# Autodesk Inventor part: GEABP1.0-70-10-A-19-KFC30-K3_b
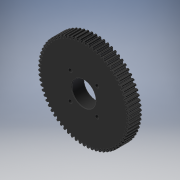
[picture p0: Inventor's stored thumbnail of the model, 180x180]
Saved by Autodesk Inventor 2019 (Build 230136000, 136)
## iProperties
Created: 2022-11
Part Number: GEABP1.0-70-10-A-19-KFC30-K3_b
Material: Generic
Catalog Web Link: www.cadenas.de
Description: GEABM, GEABMS, GEABMT, GEABP, GEABPS, GEABPT, GEABA, GEABAS, GEABAT_body-Plastic Spur Gears - Pressure Angle 20 Degrees, Module 0.5/0.8/1.0/1.5/2.0/2.5/3.0
Vendor: MISUMI
Document SubType Name: Modeling
Designer: psAdmin
Manufacturer: MISUMI
Mass: 35.1523 g
Surface Area: 122.756 cm^2
Volume: 35.1523 cm^3
Density: 1 g/cm^3
Appearance: PSOLRGB-175-175-175
Category: PARTsolutions
Company: MISUMI
Title: GEABP1.0-70-10-A-19-KFC30-K3
Author: Cadenas PARTsolutions
Comments: Plastic Spur Gears - Pressure Angle 20 Degrees, Module 0.5/0.8/1.0/1.5/2.0/2.5/3.0
PSOL_IDENT_0: {$CADENAS_DATA/23d-libs/misumi/metric/54_spur_gears/geabms20/geabms20.prj},408 {VTYP=3D},{NB=GEABP1.
PSOL_IDENT_1: 0-70-10-A-19-KFC30-K3_b},{LINA=GEABP1.0-70-10-A-19-KFC30-K3},{NN=GEABM, GEABMS, GEABMT, GEABP, GEABP
PSOL_IDENT_2: S, GEABPT, GEABA, GEABAS, GEABAT_body},{DATE=17.10.2022 23:48:33},{GEOMDATE=14.09.2022 05:11:00},{VE
PSOL_IDENT_3: RSION=},{LINEID=30},{WBVAR=MATSG,MATCR,NT,B,TS,PS,ALT1,ALT2,TPC,ALT11,ALT10,BS,ALT3,Z,J,ALT4,Q,R,S,T
PSOL_IDENT_4: ,ALT5,LFC,LTC,MALT5,ALT6,KFC,KTC,K},{WBNUMERIC=NT,B,BS,Z,J,Q,R,S,T,LFC,LTC,KFC,KTC,K}  {NB=GEABP1.0-
PSOL_IDENT_5: 70-10-A-19-KFC30-K3_b},{LINA=GEABP1.0-70-10-A-19-KFC30-K3},{KT=DUMMY},{PN=GEABP1.0-70-10-A-19-KFC30-
PSOL_IDENT_6: K3},{TYPE=GEABP},{MATSG=PW},{MATSGALG='MCN','MC Nylon','PW','Polyacetal White','PB','Polyacetal Blue'
PSOL_IDENT_7: },{MATCR=},{MATCRALG='','-','S45C','1045 Carbon Steel','SUS304','304 Stainless Steel'},{MOD=1.0},{MO
PSOL_IDENT_8: D1=1.0},{NT=70},{NTALG=15,16,18,20,22,24,25,26,28,30,32,35,36,40,45,48,50,55,60,70,75,80,90,100,120}
PSOL_IDENT_9: ,{B=10},{BALG=10,15},{TS=A},{TSALG='A','A','B','B'},{TSPN=-A},{PS=19},{PSALG='10','10','11','11','12'
PSOL_IDENT_10: ,'12','13','13','14','14','15','15','16','16','17','17','18','18','19','19','20','20','21','21','22'
PSOL_IDENT_11: ,'22','23','23','24','24','25','25','26','26','27','27','28','28'},{PSCRL='10','10','11','11','12','
PSOL_IDENT_12: 12','13','13','14','14','15','15','16','16','17','17','18','18','19','19','20','20','21','21','22','
PSOL_IDENT_13: 22','23','23','24','24','25','25','26','26','27','27','28','28'},{PSCRW='10','10','12','12','15','15'
PSOL_IDENT_14: ,'20','20'},{DD=70.0},{DD05=35},{DD08=56},{DD10=70},{DD15=105},{DD20=0},{DD25=0},{DD30=0},{D=72.0},{
PSOL_IDENT_15: D05=36},{D08=57.6},{D10=72},{D15=108},{D20=0},{D25=0},{D30=0},{G=67.50},{G05=33.75},{G08=54},{G10=67
PSOL_IDENT_16: .5},{G15=101.25},{G20=0},{G25=0},{G30=0},{H=0.0},{L=0},{LL1=0},{LL2=0.0},{M=-},{M3D=0},{P=19.00},{DD
PSOL_IDENT_17: 1=0},{CIFR=15},{CIFM=0},{CIFK=0},{CIFTAP=0},{ALT1=},{ALT1ALG='','Not applicable'},{ALT1PN=},{ALT2=},
PSOL_IDENT_18: {ALT2ALG='','Not applicable'},{TPC=N/A},{TPCALG='N/A'},{ALT2PN=},{KC=0},{ALT11=},{ALT11ALG='','Not a
PSOL_IDENT_19: pplicable'},{ALT11PN=},{DEG=0},{ALT10=},{ALT10ALG= '','Not applicable' },{ALT10PN=},{BS=0.0},{BSALG=
PSOL_IDENT_20: 0},{BSMIN=3},{BSMINALG=3.000},{BSMAX=0},{LL13D=0},{LL23D=0},{LBS=10},{ALT3=},{ALT3ALG= '','w/o Stepp
PSOL_IDENT_21: ed Hole','DHL','with DHL (Stepped Hole)','DHR','with DHR (Stepped Hole)' },{ALT3PN=},{ZJPN=},{ALT31=
PSOL_IDENT_22: 1},{ALT32=1},{Z=0},{ZALG=0},{ZMINL=21},{ZMAXL=63},{ZMINR=21},{ZMAXR=63},{ZPN=},{J=0.0},{JALG=0},{JMI
PSOL_IDENT_23: N=2},{JMAX=0},{JPN=},{ALT4=},{ALT4ALG= '','w/o WDH (Both Ends Stepped Hole)','WDH','with WDH (Both E
PSOL_IDENT_24: nds Stepped Hole)' },{ALT4PN=},{QRSTPN=},{LB=10.000},{Q=0},{QALG=0},{QMIN=21},{QMAX=63},{QPN=},{R=0}
PSOL_IDENT_25: ,{RALG=0},{RMIN=21},{RMAX=63},{RPN=},{S=0},{SALG=0},{SMIN=3},{SMAX=4},{SPN=},{T=0},{TALG=0},{TMIN=3}
PSOL_IDENT_26: ,{TMAX=0},{TPN=},{ALT5=},{ALT5ALG= '','w/o Side Slotted Hole','LFC','with LFC (Side Slotted Hole)','
PSOL_IDENT_27: LTC','with LTC (Side Slotted Hole)' },{LFC=0},{LFCALG=0},{LTC=0},{LTCALG=0},{LPCDMIN=27},{LPCDMAX=60
PSOL_IDENT_28: },{LCMAX=63},{MALT5=N/A},{MALT5ALG= 'N/A' },{LCMAX2=60},{C=0.0},{ALT5PN=},{ALT6=KFC},{ALT6ALG= '','w
PSOL_IDENT_29: /o Side Through Hole','KFC','with KFC (Side Through Hole)','KTC','with KTC (Side Through Hole)' },{A
PSOL_IDENT_30: LT6PN=-KFC},{KFTCPN=30-K3},{KFC=30},{KFCALG=[26:60/1]},{KFCPN=30},{KTC=0},{KTCALG=[0]},{KTCPN=},{KPC
PSOL_IDENT_31: DMIN1=26},{KPCDMAX1=-7},{KPCDMIN2=7},{KPCDMAX2=60},{K=3.0},{KALG=[3:6/0.5]},{KPCD=30},{KPN=-K3},{SCR
PSOL_IDENT_32: EW=0},{SCREWL=0},{AG=0},{PCD=30},{SHN=4},{SHDEG1=45},{SHDEG2=90},{PZQRDD2=19},{D1=1.285714},{D2=2.57
PSOL_IDENT_33: 1429},{D3=20},{D4=0.1},{D5=11.666667},{D6=10.769231},{D7=0.85},{D8=0.5},{D9=0.82917},{S1=15},{S2=0.5
PSOL_IDENT_34: },{KR=15}
NB: GEABP1.0-70-10-A-19-KFC30-K3_b
NN: GEABM, GEABMS, GEABMT, GEABP, GEABPS, GEABPT, GEABA, GEABAS, GEABAT_body
NT: 70
NBSYN: $PN._b
LINA: GEABP1.0-70-10-A-19-KFC30-K3
CATALOG: Misumi
PN: GEABP1.0-70-10-A-19-KFC30-K3
MATSG: Polyacetal White
MATCR: -
MOD: 1.0
B: 10
TS: A
PS: 19
DD: 70
D: 72
G: 67.5
H: 0
L: 0
LL1: 0
LL2: 0
M: -
DD1: 0
ALT1: Not applicable
ALT2: Not applicable
TPC: N/A
ALT11: Not applicable
ALT10: Not applicable
BS: 0
ALT3: w/o Stepped Hole
Z: 0
J: 0
ALT4: w/o WDH (Both Ends Stepped Hole)
Q: 0
R: 0
S: 0
T: 0
ALT5: w/o Side Slotted Hole
LFC: 0
LTC: 0
MALT5: N/A
C: 0
ALT6: with KFC (Side Through Hole)
KFC: 30
KTC: 0
K: 3
SUPPLIER: MISUMI
ARTICLENO: GEABP1.0-70-10-A-19-KFC30-K3_b
BOMINFO: GEABP1.0-70-10-A-19-KFC30-K3
CREATOR: CADENAS GmbH
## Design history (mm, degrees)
sketch "_____3"
  geometry: L1 (10, 0)-(0, 0); L2 (0, 0)-(0, 35.5); L3 (0, 35.5)-(0.67, 38); L4 (0.67, 38)-(9.33, 38); L5 (9.33, 38)-(10, 35.5); L6 (10, 35.5)-(10, 0); L7 (10, 0)-(0, 0)
  constraints: 14 end point
revolve "Revolution1" sketch "_____3" stored, may be unused: angle "d0" = 360 deg
sketch "_____12"
  geometry: C1 r 144 at (0, 0); A1 r 0.1 centre (-35.877, 1.285) between (-35.977, 1.288) and (-35.921, 1.195); A2 r 11.667 centre (-30.756, 11.656) between (-35.921, 1.195) and (-34.991, 0.785); A3 r 0.829 centre (-34.69, 1.558) between (-34.991, 0.785) and (-34.876, 0.75); A4 r 10.769 centre (-37.286, -9.746) between (-34.102, 0.542) and (-34.876, 0.75); A5 r 0.5 centre (-34.25, 0.064) between (-33.75, 0.063) and (-34.102, 0.542); A6 r 33.75 centre (0, 0) between (-33.75, 0.063) and (-33.75, -0.063); A7 r 0.5 centre (-34.25, -0.064) between (-34.102, -0.542) and (-33.75, -0.063); A8 r 10.769 centre (-37.286, 9.746) between (-34.876, -0.75) and (-34.102, -0.542); A9 r 0.829 centre (-34.69, -1.558) between (-34.876, -0.75) and (-34.991, -0.785); A10 r 11.667 centre (-30.756, -11.656) between (-34.991, -0.785) and (-35.921, -1.195); A11 r 0.1 centre (-35.877, -1.285) between (-35.921, -1.195) and (-35.977, -1.288); A12 r 36 centre (0, 0) between (-35.977, -1.288) and (-35.948, -1.942); A13 r 0.1 centre (-35.848, -1.936) between (-35.948, -1.942) and (-35.884, -2.03); A14 r 11.667 centre (-31.677, 8.852) between (-35.884, -2.03) and (-34.921, -2.354); A15 r 0.829 centre (-34.69, -1.558) between (-34.921, -2.354) and (-34.802, -2.379); A16 r 10.769 centre (-36.262, -13.049) between (-34.013, -2.517) and (-34.802, -2.379); A17 r 0.5 centre (-34.118, -3.006) between (-33.62, -2.963) and (-34.013, -2.517); A18 r 33.75 centre (0, 0) between (-33.62, -2.963) and (-33.608, -3.088); A19 r 0.5 centre (-34.106, -3.134) between (-33.916, -3.596) and (-33.608, -3.088); A20 r 10.769 centre (-38.009, 6.365) between (-34.668, -3.873) and (-33.916, -3.596); A21 r 0.829 centre (-34.411, -4.661) between (-34.668, -3.873) and (-34.78, -3.919); A22 r 11.667 centre (-29.587, -14.366) between (-34.78, -3.919) and (-35.67, -4.41); A23 r 0.1 centre (-35.617, -4.496) between (-35.67, -4.41) and (-35.717, -4.508); A24 r 36 centre (0, 0) between (-35.717, -4.508) and (-35.629, -5.156); A25 r 0.1 centre (-35.53, -5.142) between (-35.629, -5.156) and (-35.557, -5.238); A26 r 11.667 centre (-32.343, 5.977) between (-35.557, -5.238) and (-34.569, -5.475); A27 r 0.829 centre (-34.411, -4.661) between (-34.569, -5.475) and (-34.449, -5.49); A28 r 10.769 centre (-34.946, -16.247) between (-33.651, -5.556) and (-34.449, -5.49); A29 r 0.5 centre (-33.711, -6.053) between (-33.219, -5.964) and (-33.651, -5.556); A30 r 33.75 centre (0, 0) between (-33.219, -5.964) and (-33.196, -6.088); A31 r 0.5 centre (-33.688, -6.178) between (-33.457, -6.622) and (-33.196, -6.088); A32 r 10.769 centre (-38.427, 2.932) between (-34.181, -6.965) and (-33.457, -6.622); A33 r 0.829 centre (-33.855, -7.727) between (-34.181, -6.965) and (-34.289, -7.021); A34 r 11.667 centre (-28.18, -16.96) between (-34.289, -7.021) and (-35.131, -7.59); A35 r 0.1 centre (-35.071, -7.67) between (-35.131, -7.59) and (-35.169, -7.692); A36 r 36 centre (0, 0) between (-35.169, -7.692) and (-35.023, -8.329); A37 r 0.1 centre (-34.926, -8.306) between (-35.023, -8.329) and (-34.945, -8.404); A38 r 11.667 centre (-32.749, 3.054) between (-34.945, -8.404) and (-33.939, -8.552); A39 r 0.829 centre (-33.855, -7.727) between (-33.939, -8.552) and (-33.818, -8.555); A40 r 10.769 centre (-33.349, -19.314) between (-33.017, -8.55) and (-33.818, -8.555); A41 r 0.5 centre (-33.033, -9.05) between (-32.55, -8.918) and (-33.017, -8.55); A42 r 33.75 centre (0, 0) between (-32.55, -8.918) and (-32.517, -9.039); A43 r 0.5 centre (-32.999, -9.173) between (-32.729, -9.594) and (-32.517, -9.039); A44 r 10.769 centre (-38.535, -0.524) between (-33.419, -10.001) and (-32.729, -9.594); A45 r 0.829 centre (-33.026, -10.731) between (-33.419, -10.001) and (-33.521, -10.066); A46 r 11.667 centre (-26.547, -19.418) between (-33.521, -10.066) and (-34.309, -10.709); A47 r 0.1 centre (-34.242, -10.783) between (-34.309, -10.709) and (-34.338, -10.813); A48 r 36 centre (0, 0) between (-34.338, -10.813) and (-34.136, -11.435); A49 r 0.1 centre (-34.041, -11.403) between (-34.136, -11.435) and (-34.051, -11.503); A50 r 11.667 centre (-32.89, 0.106) between (-34.051, -11.503) and (-33.036, -11.56); A51 r 0.829 centre (-33.026, -10.731) between (-33.036, -11.56) and (-32.915, -11.552); A52 r 10.769 centre (-31.484, -22.226) between (-32.118, -11.476) and (-32.915, -11.552); A53 r 0.5 centre (-32.088, -11.975) between (-31.62, -11.8) and (-32.118, -11.476); A54 r 33.75 centre (0, 0) between (-31.62, -11.8) and (-31.576, -11.918); A55 r 0.5 centre (-32.044, -12.094) between (-31.737, -12.49) and (-31.576, -11.918); A56 r 10.769 centre (-38.333, -3.977) between (-32.388, -12.956) and (-31.737, -12.49); A57 r 0.829 centre (-31.931, -13.648) between (-32.388, -12.956) and (-32.484, -13.03); A58 r 11.667 centre (-24.699, -21.72) between (-32.484, -13.03) and (-33.211, -13.741); A59 r 0.1 centre (-33.138, -13.809) between (-33.211, -13.741) and (-33.23, -13.848); A60 r 36 centre (0, 0) between (-33.23, -13.848) and (-32.973, -14.449); A61 r 0.1 centre (-32.882, -14.409) between (-32.973, -14.449) and (-32.883, -14.509); A62 r 11.667 centre (-32.768, -2.843) between (-32.883, -14.509) and (-31.867, -14.475); A63 r 0.829 centre (-31.931, -13.648) between (-31.867, -14.475) and (-31.747, -14.456); A64 r 10.769 centre (-29.365, -24.959) between (-30.96, -14.308) and (-31.747, -14.456)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; 1 further point
  constraints: 1680 point on circle, 841 centre point
extrude "Extrusion1" cut sketch "_____12" distance "d1" = 10; taper "d2" = 0 deg
sketch "Sketch3"
  geometry: 1 further point
hole "Hole1" sketch "Sketch3" at (0, 0) diameter "d3" = 19; stored, may be unused: countersink angle "d7" = 90 deg, drill point angle "d9" = 0 deg; dims "d4" = 6, "d5" = 4, "d6" = 2, "d8" = 10
sketch "_____5"
  geometry: L1 (500, 0)-(-500, 0); L2 (9.7, 9.5)-(10, 9.5); L3 (10, 9.5)-(10, 9.8); L4 (10, 9.8)-(9.7, 9.5)
  constraints: 8 end point
revolve "Revolution2" sketch "_____5" stored, may be unused: angle "d10" = 360 deg
sketch "_____13"
  geometry: L1 (500, 0)-(-500, 0); L2 (0, 9.8)-(0, 9.5); L3 (0, 9.5)-(0.3, 9.5); L4 (0.3, 9.5)-(0, 9.8)
  constraints: 8 end point
revolve "Revolution3" sketch "_____13" stored, may be unused: angle "d11" = 360 deg
sketch "Sketch6"
  geometry: 1 further point
hole "Hole2" sketch "Sketch6" at (-9.087, 11.934) diameter "d12" = 3; stored, may be unused: countersink angle "d16" = 90 deg, drill point angle "d18" = 0 deg; dims "d13" = 6, "d14" = 4, "d15" = 2, "d17" = 10
pattern_linear "Rectangular Pattern1" dims "d21" = 21.2132, "d24" = 21.2132
body "Solid1"
